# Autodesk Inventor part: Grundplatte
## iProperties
Shininess: 64.0
Length Units: 11269
Angle Units: 11279
Time Units: 11290
Mass Units: 11283
Length Display Precision: 3
Angle Display Precision: 2
Compacted: True
Part Number: Grundplatte
Document SubType Name: Modeling
Created: 2005-08
Material: Standard
Designer: Kumpf
Density: 0.0
Volumn: 0.0
Area: 0.0
PropertySet Name: Model Information
Control State: 0
Master: False
Checked Out: False
Author: Kumpf
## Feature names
1. Extrusion1
2. Bohrung2 [Hole]
3. Fase1 [Chamfer]
4. Bohrung3 [Hole]
5. Extrusion2
